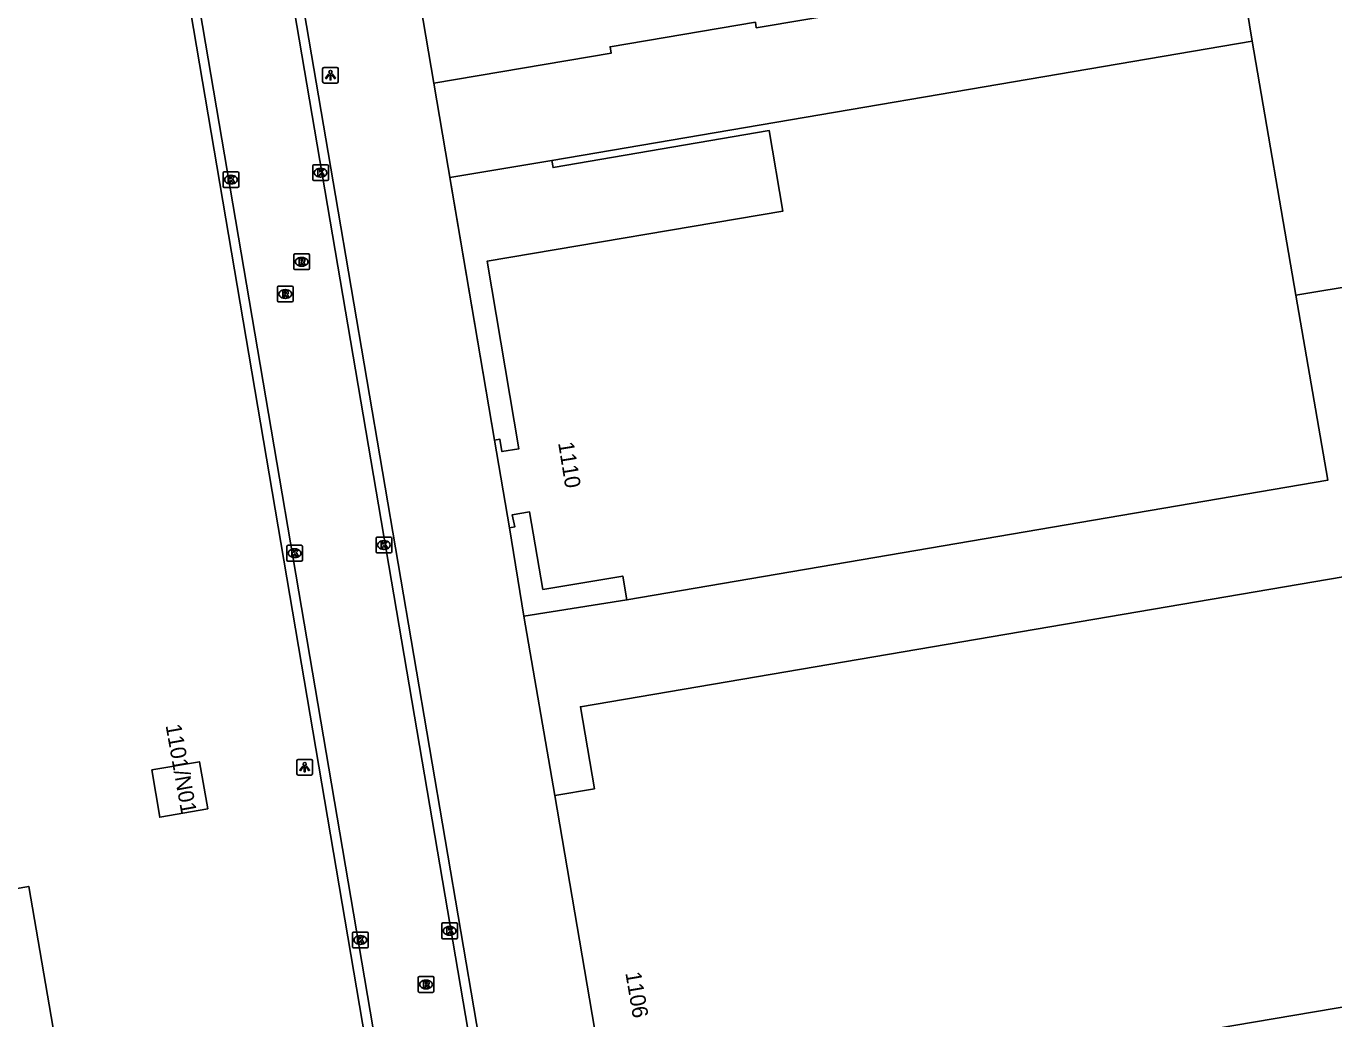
# Model space of a CAD drawing. Extents: x 154324 to 155743, y 382939 to 384183.
# Drawn here: x 154922.8 to 155006.1, y 383284.2 to 383347.4 of the extents above; entities that cross this region are included whole.
import ezdxf

# ---------------------------------------------------------------- set-up
doc = ezdxf.new("R2010")
doc.units = 0
for name, color, linetype in [('IMGEO_Grasland_agrarisch', 7, 'Continuous'), ('IMGEO_Kolk', 7, 'Continuous'), ('IMGEO_Lichtpunt', 7, 'Continuous'), ('IMGEO_Pand', 7, 'Continuous'), ('IMGEO_Pand_nummerreeks', 7, 'Continuous'), ('IMGEO_Pand_overbouw', 7, 'Continuous'), ('IMGEO_Parkeervlak_open', 7, 'Continuous'), ('IMGEO_Rijbaan_lokaal_gesloten', 7, 'Continuous'), ('IMGEO_Rijbaan_lokaal_open', 7, 'Continuous'), ('IMGEO_Rioolput', 7, 'Continuous')]:
    doc.layers.add(name, color=color, linetype=linetype)

msp = doc.modelspace()

# ---------------------------------------------------------------- linework, layer by layer
at = {"layer": 'IMGEO_Grasland_agrarisch'}
for points in [[(155000.868, 383346.436), (154999.878, 383352.447)], [(155062.526, 383340.029), (155003.646, 383330.283)]]:
    msp.add_lwpolyline(points, dxfattribs=at)
at = {"layer": 'IMGEO_Kolk'}
for p, q in [((154941.026, 383337.649), (154941.026, 383338.501)), ((154941.101, 383338.575), (154941.953, 383338.575)), ((154941.514, 383338.355), (154941.539, 383338.355)), ((154942.027, 383338.501), (154942.027, 383337.649)), ((154935.32, 383337.207), (154935.32, 383338.059)), ((154935.395, 383338.133), (154936.247, 383338.133)), ((154935.808, 383337.913), (154935.833, 383337.913)), ((154936.321, 383338.059), (154936.321, 383337.207)), ((154941.953, 383337.575), (154941.101, 383337.575)), ((154941.537, 383337.795), (154941.512, 383337.795)), ((154936.247, 383337.133), (154935.395, 383337.133)), ((154935.831, 383337.353), (154935.806, 383337.353)), ((154939.374, 383313.426), (154939.374, 383314.278)), ((154939.449, 383314.352), (154940.301, 383314.352)), ((154939.862, 383314.132), (154939.887, 383314.132)), ((154940.375, 383314.278), (154940.375, 383313.426)), ((154945.059, 383313.946), (154945.059, 383314.798)), ((154945.134, 383314.872), (154945.986, 383314.872)), ((154945.547, 383314.652), (154945.572, 383314.652)), ((154946.06, 383314.798), (154946.06, 383313.946)), ((154940.301, 383313.352), (154939.449, 383313.352)), ((154939.885, 383313.572), (154939.86, 383313.572)), ((154945.986, 383313.872), (154945.134, 383313.872)), ((154945.57, 383314.092), (154945.545, 383314.092)), ((154949.247, 383289.386), (154949.247, 383290.238)), ((154949.322, 383290.312), (154950.174, 383290.312)), ((154949.735, 383290.092), (154949.76, 383290.092)), ((154950.248, 383290.238), (154950.248, 383289.386)), ((154943.56, 383288.804), (154943.56, 383289.656)), ((154943.635, 383289.73), (154944.487, 383289.73)), ((154944.048, 383289.51), (154944.073, 383289.51)), ((154944.561, 383289.656), (154944.561, 383288.804)), ((154950.174, 383289.312), (154949.322, 383289.312)), ((154949.758, 383289.532), (154949.733, 383289.532)), ((154944.487, 383288.73), (154943.635, 383288.73)), ((154944.071, 383288.95), (154944.046, 383288.95))]:
    msp.add_line(p, q, dxfattribs=at)
for points in [[(154941.026, 383337.649), (154941.026, 383338.501)], [(154941.101, 383338.575), (154941.953, 383338.575)], [(154941.347, 383338.275), (154941.47, 383338.275), (154941.47, 383338.124), (154941.6, 383338.275), (154941.764, 383338.275), (154941.618, 383338.124), (154941.771, 383337.875), (154941.619, 383337.875), (154941.534, 383338.039), (154941.47, 383337.972), (154941.47, 383337.875), (154941.347, 383337.875), (154941.347, 383338.275)], [(154942.027, 383338.501), (154942.027, 383337.649)], [(154935.32, 383337.207), (154935.32, 383338.059)], [(154935.395, 383338.133), (154936.247, 383338.133)], [(154935.641, 383337.833), (154935.764, 383337.833), (154935.764, 383337.682), (154935.894, 383337.833), (154936.058, 383337.833), (154935.912, 383337.682), (154936.065, 383337.433), (154935.913, 383337.433), (154935.828, 383337.597), (154935.764, 383337.53), (154935.764, 383337.433), (154935.641, 383337.433), (154935.641, 383337.833)], [(154936.321, 383338.059), (154936.321, 383337.207)], [(154941.953, 383337.575), (154941.101, 383337.575)], [(154936.247, 383337.133), (154935.395, 383337.133)], [(154939.374, 383313.426), (154939.374, 383314.278)], [(154939.449, 383314.352), (154940.301, 383314.352)], [(154940.375, 383314.278), (154940.375, 383313.426)], [(154945.059, 383313.946), (154945.059, 383314.798)], [(154945.134, 383314.872), (154945.986, 383314.872)], [(154945.38, 383314.572), (154945.503, 383314.572), (154945.503, 383314.421), (154945.633, 383314.572), (154945.797, 383314.572), (154945.651, 383314.421), (154945.804, 383314.172), (154945.652, 383314.172), (154945.567, 383314.336), (154945.503, 383314.269), (154945.503, 383314.172), (154945.38, 383314.172), (154945.38, 383314.572)], [(154946.06, 383314.798), (154946.06, 383313.946)], [(154940.301, 383313.352), (154939.449, 383313.352)], [(154939.695, 383314.052), (154939.818, 383314.052), (154939.818, 383313.901), (154939.948, 383314.052), (154940.112, 383314.052), (154939.966, 383313.901), (154940.119, 383313.652), (154939.967, 383313.652), (154939.882, 383313.816), (154939.818, 383313.749), (154939.818, 383313.652), (154939.695, 383313.652), (154939.695, 383314.052)], [(154945.986, 383313.872), (154945.134, 383313.872)], [(154949.247, 383289.386), (154949.247, 383290.238)], [(154949.322, 383290.312), (154950.174, 383290.312)], [(154949.568, 383290.012), (154949.691, 383290.012), (154949.691, 383289.861), (154949.821, 383290.012), (154949.985, 383290.012), (154949.839, 383289.861), (154949.992, 383289.612), (154949.84, 383289.612), (154949.755, 383289.776), (154949.691, 383289.709), (154949.691, 383289.612), (154949.568, 383289.612), (154949.568, 383290.012)], [(154950.248, 383290.238), (154950.248, 383289.386)], [(154943.56, 383288.804), (154943.56, 383289.656)], [(154943.635, 383289.73), (154944.487, 383289.73)], [(154943.881, 383289.43), (154944.004, 383289.43), (154944.004, 383289.279), (154944.134, 383289.43), (154944.298, 383289.43), (154944.152, 383289.279), (154944.305, 383289.03), (154944.153, 383289.03), (154944.068, 383289.194), (154944.004, 383289.127), (154944.004, 383289.03), (154943.881, 383289.03), (154943.881, 383289.43)], [(154944.561, 383289.656), (154944.561, 383288.804)], [(154950.174, 383289.312), (154949.322, 383289.312)], [(154944.487, 383288.73), (154943.635, 383288.73)]]:
    msp.add_lwpolyline(points, dxfattribs=at)
for centre, start, end in [((154941.103, 383338.499), 91.55205, 178.44795), ((154941.103, 383338.499), 91.55205, 178.44795), ((154941.951, 383338.499), 1.55205, 88.44795), ((154941.951, 383338.499), 1.55205, 88.44795), ((154935.397, 383338.057), 91.55205, 178.44795), ((154935.397, 383338.057), 91.55205, 178.44795), ((154936.245, 383338.057), 1.55205, 88.44795), ((154936.245, 383338.057), 1.55205, 88.44795), ((154941.103, 383337.651), 181.55205, 268.44795), ((154941.103, 383337.651), 181.55205, 268.44795), ((154941.951, 383337.651), 271.55205, 358.44795), ((154941.951, 383337.651), 271.55205, 358.44795), ((154935.397, 383337.209), 181.55205, 268.44795), ((154935.397, 383337.209), 181.55205, 268.44795), ((154936.245, 383337.209), 271.55205, 358.44795), ((154936.245, 383337.209), 271.55205, 358.44795), ((154939.451, 383314.276), 91.55205, 178.44795), ((154939.451, 383314.276), 91.55205, 178.44795), ((154940.299, 383314.276), 1.55205, 88.44795), ((154940.299, 383314.276), 1.55205, 88.44795), ((154945.136, 383314.796), 91.55205, 178.44795), ((154945.136, 383314.796), 91.55205, 178.44795), ((154945.984, 383314.796), 1.55205, 88.44795), ((154945.984, 383314.796), 1.55205, 88.44795), ((154939.451, 383313.428), 181.55205, 268.44795), ((154939.451, 383313.428), 181.55205, 268.44795), ((154940.299, 383313.428), 271.55205, 358.44795), ((154940.299, 383313.428), 271.55205, 358.44795), ((154945.136, 383313.948), 181.55205, 268.44795), ((154945.136, 383313.948), 181.55205, 268.44795), ((154945.984, 383313.948), 271.55205, 358.44795), ((154945.984, 383313.948), 271.55205, 358.44795), ((154949.324, 383290.236), 91.55205, 178.44795), ((154949.324, 383290.236), 91.55205, 178.44795), ((154950.172, 383290.236), 1.55205, 88.44795), ((154950.172, 383290.236), 1.55205, 88.44795), ((154943.637, 383289.654), 91.55205, 178.44795), ((154943.637, 383289.654), 91.55205, 178.44795), ((154944.485, 383289.654), 1.55205, 88.44795), ((154944.485, 383289.654), 1.55205, 88.44795), ((154949.324, 383289.388), 181.55205, 268.44795), ((154949.324, 383289.388), 181.55205, 268.44795), ((154950.172, 383289.388), 271.55205, 358.44795), ((154950.172, 383289.388), 271.55205, 358.44795), ((154943.637, 383288.806), 181.55205, 268.44795), ((154943.637, 383288.806), 181.55205, 268.44795), ((154944.485, 383288.806), 271.55205, 358.44795), ((154944.485, 383288.806), 271.55205, 358.44795)]:
    msp.add_arc(centre, 0.0765, start, end, dxfattribs=at)
for centre, major_axis, ratio, start_param, end_param in [((154941.513, 383338.075), (-0.387, 0.002), 0.722429, 4.712389, 7.853982), ((154941.538, 383338.075), (-0.39, 0.002), 0.717154, 1.570796, 4.712389), ((154935.807, 383337.633), (-0.387, 0.002), 0.722429, 4.712389, 7.853982), ((154935.832, 383337.633), (-0.39, 0.002), 0.717154, 1.570796, 4.712389), ((154939.861, 383313.852), (-0.387, 0.002), 0.722429, 4.712389, 7.853982), ((154939.886, 383313.852), (-0.39, 0.002), 0.717154, 1.570796, 4.712389), ((154945.546, 383314.372), (-0.387, 0.002), 0.722429, 4.712389, 7.853982), ((154945.571, 383314.372), (-0.39, 0.002), 0.717154, 1.570796, 4.712389), ((154949.734, 383289.812), (-0.387, 0.002), 0.722429, 4.712389, 7.853982), ((154949.759, 383289.812), (-0.39, 0.002), 0.717154, 1.570796, 4.712389), ((154944.047, 383289.23), (-0.387, 0.002), 0.722429, 4.712389, 7.853982), ((154944.072, 383289.23), (-0.39, 0.002), 0.717154, 1.570796, 4.712389)]:
    msp.add_ellipse(centre, major_axis=major_axis, ratio=ratio, start_param=start_param, end_param=end_param, dxfattribs=at)
at = {"layer": 'IMGEO_Lichtpunt'}
for p, q in [((154941.66, 383344.683), (154941.66, 383343.876)), ((154941.66, 383344.683), (154941.66, 383343.876)), ((154942.562, 383344.778), (154941.754, 383344.778)), ((154942.562, 383344.778), (154941.754, 383344.778)), ((154942.656, 383343.876), (154942.656, 383344.683)), ((154942.656, 383343.876), (154942.656, 383344.683)), ((154941.754, 383343.782), (154942.562, 383343.782)), ((154941.754, 383343.782), (154942.562, 383343.782)), ((154940.016, 383300.629), (154940.016, 383299.822)), ((154940.016, 383300.629), (154940.016, 383299.822)), ((154940.918, 383300.724), (154940.11, 383300.724)), ((154940.918, 383300.724), (154940.11, 383300.724)), ((154941.012, 383299.822), (154941.012, 383300.629)), ((154941.012, 383299.822), (154941.012, 383300.629)), ((154940.11, 383299.728), (154940.918, 383299.728)), ((154940.11, 383299.728), (154940.918, 383299.728))]:
    msp.add_line(p, q, dxfattribs=at)
for points in [[(154942.034, 383344.347), (154942.073, 383344.319), (154941.885, 383344.057), (154941.847, 383344.084), (154942.034, 383344.347)], [(154942.136, 383344.299), (154942.183, 383344.299), (154942.183, 383343.977), (154942.136, 383343.977), (154942.136, 383344.299)], [(154942.246, 383344.319), (154942.284, 383344.346), (154942.471, 383344.084), (154942.432, 383344.056), (154942.246, 383344.319)], [(154940.39, 383300.293), (154940.429, 383300.265), (154940.241, 383300.003), (154940.203, 383300.03), (154940.39, 383300.293)], [(154940.492, 383300.245), (154940.539, 383300.245), (154940.539, 383299.923), (154940.492, 383299.923), (154940.492, 383300.245)], [(154940.602, 383300.265), (154940.64, 383300.292), (154940.827, 383300.03), (154940.788, 383300.002), (154940.602, 383300.265)]]:
    msp.add_lwpolyline(points, dxfattribs=at)
for centre in [(154942.159, 383344.481), (154940.515, 383300.427)]:
    msp.add_circle(centre, 0.0994, dxfattribs=at)
for centre, start, end in [((154941.754, 383344.683), 90, 180), ((154941.754, 383344.683), 90, 180), ((154942.562, 383344.683), 0, 90), ((154942.562, 383344.683), 0, 90), ((154941.754, 383343.876), 180, 270), ((154941.754, 383343.876), 180, 270), ((154942.562, 383343.876), 270, 0), ((154942.562, 383343.876), 270, 360), ((154940.11, 383300.629), 90, 180), ((154940.11, 383300.629), 90, 180), ((154940.918, 383300.629), 0, 90), ((154940.918, 383300.629), 0, 90), ((154940.11, 383299.822), 180, 270), ((154940.11, 383299.822), 180, 270), ((154940.918, 383299.822), 270, 0), ((154940.918, 383299.822), 270, 360)]:
    msp.add_arc(centre, 0.0946, start, end, dxfattribs=at)
at = {"layer": 'IMGEO_Pand'}
for points in [[(154948.75, 383343.779), (154944.993, 383365.869), (154944.925, 383366.268), (154965.468, 383369.782), (154964.539, 383375.316)], [(154999.878, 383352.447), (154969.278, 383347.303), (154969.219, 383347.653), (154959.969, 383346.088), (154960.036, 383345.69), (154948.75, 383343.779)], [(154952.604, 383321.047), (154952.949, 383321.105), (154953.081, 383320.316), (154954.156, 383320.496), (154952.132, 383332.433), (154970.973, 383335.629), (154970.103, 383340.756), (154956.338, 383338.399), (154956.261, 383338.852), (155000.868, 383346.436)], [(155003.646, 383330.283), (155000.868, 383346.436)], [(154841.851, 383345.321), (154852.853, 383280.684), (154854.938, 383281.039), (154922.938, 383292.639), (154927.907, 383263.724), (154927.942, 383263.507), (154923.572, 383260.288), (154926.413, 383256.439), (154924.778, 383255.22), (154927.17, 383252.008), (154925.538, 383250.794), (154927.916, 383247.585), (154926.283, 383246.367), (154929.131, 383242.58), (154931.183, 383244.108), (154931.296, 383243.969), (154938.169, 383203.279), (154923.048, 383200.725), (154925.906, 383183.809)], [(155003.646, 383330.283), (155005.673, 383318.494), (154961.037, 383310.872), (154960.776, 383312.399), (154955.689, 383311.55), (154954.834, 383316.483), (154953.74, 383316.294), (154953.892, 383315.524), (154953.555, 383315.462)], [(154953.555, 383315.462), (154952.604, 383321.047)], [(154956.449, 383298.428), (154958.963, 383298.857), (154958.072, 383304.074), (155006.663, 383312.344), (155011.213, 383285.747), (154970.24, 383278.793), (154971.18, 383273.272), (154961.04, 383271.548)], [(154930.785, 383300.07), (154933.808, 383300.574), (154934.341, 383297.582), (154931.29, 383297.039), (154930.785, 383300.07)], [(154961.04, 383271.548), (154956.449, 383298.428)]]:
    msp.add_lwpolyline(points, dxfattribs=at)
at = {"layer": 'IMGEO_Pand_overbouw'}
for points in [[(154956.261, 383338.852), (154949.764, 383337.775), (154952.604, 383321.047), (154952.949, 383321.105), (154953.081, 383320.316), (154954.156, 383320.496), (154952.132, 383332.433), (154970.973, 383335.629), (154970.103, 383340.756), (154956.338, 383338.399)], [(154961.037, 383310.872), (154960.776, 383312.399), (154955.689, 383311.55), (154954.834, 383316.483), (154953.74, 383316.294), (154953.892, 383315.524), (154953.555, 383315.462), (154954.479, 383309.839)]]:
    msp.add_lwpolyline(points, close=True, dxfattribs=at)
at = {"layer": 'IMGEO_Parkeervlak_open'}
for points in [[(154948.75, 383343.779), (154952.604, 383321.047)], [(154956.449, 383298.428), (154954.479, 383309.839), (154953.555, 383315.462)]]:
    msp.add_lwpolyline(points, dxfattribs=at)
at = {"layer": 'IMGEO_Rijbaan_lokaal_gesloten'}
for points in [[(154937.891, 383359.922), (154961.836, 383219.4)], [(154958.22, 383204.737), (154957.681, 383208.024), (154956.051, 383217.962), (154933.662, 383349.45), (154932.04, 383358.964)]]:
    msp.add_lwpolyline(points, dxfattribs=at)
at = {"layer": 'IMGEO_Rijbaan_lokaal_open'}
for points in [[(154962.428, 383219.494), (154942.478, 383336.616), (154938.491, 383360.02)], [(154957.636, 383205.007), (154955.126, 383219.621), (154933.063, 383349.385), (154931.446, 383358.867)]]:
    msp.add_lwpolyline(points, dxfattribs=at)
at = {"layer": 'IMGEO_Rioolput'}
for p, q in [((154939.823, 383331.974), (154939.823, 383332.826)), ((154939.898, 383332.9), (154940.75, 383332.9)), ((154940.311, 383332.68), (154940.336, 383332.68)), ((154940.824, 383332.826), (154940.824, 383331.974)), ((154940.75, 383331.9), (154939.898, 383331.9)), ((154940.334, 383332.12), (154940.309, 383332.12)), ((154938.778, 383329.924), (154938.778, 383330.776)), ((154938.853, 383330.85), (154939.705, 383330.85)), ((154939.779, 383330.776), (154939.779, 383329.924)), ((154939.289, 383330.07), (154939.264, 383330.07)), ((154939.266, 383330.63), (154939.291, 383330.63)), ((154939.705, 383329.85), (154938.853, 383329.85)), ((154947.746, 383285.971), (154947.746, 383286.823)), ((154947.821, 383286.897), (154948.673, 383286.897)), ((154948.234, 383286.677), (154948.259, 383286.677)), ((154948.747, 383286.823), (154948.747, 383285.971)), ((154948.673, 383285.897), (154947.821, 383285.897)), ((154948.257, 383286.117), (154948.232, 383286.117))]:
    msp.add_line(p, q, dxfattribs=at)
for points in [[(154939.823, 383331.974), (154939.823, 383332.826)], [(154939.898, 383332.9), (154940.75, 383332.9)], [(154940.412, 383332.598), (154940.16, 383332.6), (154940.16, 383332.2)], [(154940.338, 383332.519), (154940.284, 383332.519), (154940.284, 383332.438)], [(154940.284, 383332.438), (154940.336, 383332.438)], [(154940.824, 383332.826), (154940.824, 383331.974)], [(154940.75, 383331.9), (154939.898, 383331.9)], [(154940.16, 383332.2), (154940.284, 383332.2), (154940.284, 383332.362), (154940.295, 383332.362)], [(154940.342, 383332.333), (154940.413, 383332.2), (154940.553, 383332.2), (154940.488, 383332.326)], [(154938.778, 383329.924), (154938.778, 383330.776)], [(154938.853, 383330.85), (154939.705, 383330.85)], [(154939.779, 383330.776), (154939.779, 383329.924)], [(154939.367, 383330.548), (154939.115, 383330.55), (154939.115, 383330.15)], [(154939.115, 383330.15), (154939.239, 383330.15), (154939.239, 383330.312), (154939.25, 383330.312)], [(154939.293, 383330.469), (154939.239, 383330.469), (154939.239, 383330.388)], [(154939.239, 383330.388), (154939.291, 383330.388)], [(154939.297, 383330.283), (154939.368, 383330.15), (154939.508, 383330.15), (154939.443, 383330.276)], [(154939.705, 383329.85), (154938.853, 383329.85)], [(154947.746, 383285.971), (154947.746, 383286.823)], [(154947.821, 383286.897), (154948.673, 383286.897)], [(154948.747, 383286.823), (154948.747, 383285.971)], [(154948.673, 383285.897), (154947.821, 383285.897)], [(154948.335, 383286.595), (154948.083, 383286.597), (154948.083, 383286.197)], [(154948.083, 383286.197), (154948.207, 383286.197), (154948.207, 383286.359), (154948.218, 383286.359)], [(154948.261, 383286.516), (154948.207, 383286.516), (154948.207, 383286.435)], [(154948.207, 383286.435), (154948.259, 383286.435)], [(154948.265, 383286.33), (154948.336, 383286.197), (154948.476, 383286.197), (154948.411, 383286.323)]]:
    msp.add_lwpolyline(points, dxfattribs=at)
for centre, radius, start, end in [((154939.9, 383332.824), 0.0765, 91.55205, 178.44795), ((154939.9, 383332.824), 0.0765, 91.55205, 178.44795), ((154940.32, 383332.627), 0.19, 274.7715, 282.96867), ((154940.344, 383332.423), 0.0964, 77.00612, 93.18647), ((154940.358, 383332.48), 0.0378, 276.66336, 79.67722), ((154940.411, 383332.488), 0.109, 350.36119, 89.41601), ((154940.409, 383332.488), 0.112, 277.58423, 350.98172), ((154940.748, 383332.824), 0.0765, 1.55205, 88.44795), ((154940.748, 383332.824), 0.0765, 1.55205, 88.44795), ((154939.9, 383331.976), 0.0765, 181.55205, 268.44795), ((154939.9, 383331.976), 0.0765, 181.55205, 268.44795), ((154940.294, 383332.309), 0.0533, 26.02933, 88.69889), ((154940.393, 383332.273), 0.108, 29.51342, 73.79051), ((154940.748, 383331.976), 0.0765, 271.55205, 358.44795), ((154940.748, 383331.976), 0.0765, 271.55205, 358.44795), ((154938.855, 383330.774), 0.0765, 91.55205, 178.44795), ((154938.855, 383330.774), 0.0765, 91.55205, 178.44795), ((154939.703, 383330.774), 0.0765, 1.55205, 88.44795), ((154939.703, 383330.774), 0.0765, 1.55205, 88.44795), ((154939.249, 383330.259), 0.0533, 26.02933, 88.69889), ((154939.275, 383330.577), 0.19, 274.7715, 282.96867), ((154939.299, 383330.373), 0.0964, 77.00612, 93.18647), ((154939.313, 383330.43), 0.0378, 276.66336, 79.67722), ((154939.366, 383330.438), 0.109, 350.36119, 89.41601), ((154939.364, 383330.438), 0.112, 277.58423, 350.98172), ((154939.348, 383330.223), 0.108, 29.51342, 73.79051), ((154938.855, 383329.926), 0.0765, 181.55205, 268.44795), ((154938.855, 383329.926), 0.0765, 181.55205, 268.44795), ((154939.703, 383329.926), 0.0765, 271.55205, 358.44795), ((154939.703, 383329.926), 0.0765, 271.55205, 358.44795), ((154947.823, 383286.821), 0.0765, 91.55205, 178.44795), ((154947.823, 383286.821), 0.0765, 91.55205, 178.44795), ((154948.671, 383286.821), 0.0765, 1.55205, 88.44795), ((154948.671, 383286.821), 0.0765, 1.55205, 88.44795), ((154947.823, 383285.973), 0.0765, 181.55205, 268.44795), ((154947.823, 383285.973), 0.0765, 181.55205, 268.44795), ((154948.217, 383286.306), 0.0533, 26.02933, 88.69889), ((154948.243, 383286.624), 0.19, 274.7715, 282.96867), ((154948.267, 383286.42), 0.0964, 77.00612, 93.18647), ((154948.281, 383286.477), 0.0378, 276.66336, 79.67722), ((154948.334, 383286.485), 0.109, 350.36119, 89.41601), ((154948.332, 383286.485), 0.112, 277.58423, 350.98172), ((154948.316, 383286.27), 0.108, 29.51342, 73.79051), ((154948.671, 383285.973), 0.0765, 271.55205, 358.44795), ((154948.671, 383285.973), 0.0765, 271.55205, 358.44795)]:
    msp.add_arc(centre, radius, start, end, dxfattribs=at)
for centre, major_axis, ratio, start_param, end_param in [((154940.31, 383332.4), (-0.387, 0.002), 0.722429, 4.712389, 7.853982), ((154940.335, 383332.4), (-0.39, 0.002), 0.717154, 1.570796, 4.712389), ((154939.265, 383330.35), (-0.387, 0.002), 0.722429, 4.712389, 7.853982), ((154939.29, 383330.35), (-0.39, 0.002), 0.717154, 1.570796, 4.712389), ((154948.233, 383286.397), (-0.387, 0.002), 0.722429, 4.712389, 7.853982), ((154948.258, 383286.397), (-0.39, 0.002), 0.717154, 1.570796, 4.712389)]:
    msp.add_ellipse(centre, major_axis=major_axis, ratio=ratio, start_param=start_param, end_param=end_param, dxfattribs=at)

# ---------------------------------------------------------------- texts
at = {"layer": 'IMGEO_Pand_nummerreeks'}
for s, rotation, p in [('1110', 279.28457, (154956.652, 383320.871)), ('1101/N01', 280.10844, (154931.653, 383302.889)), ('1106', 279.69162, (154960.935, 383287.131))]:
    msp.add_text(s, height=1, rotation=rotation, dxfattribs=at).set_placement(p)

doc.saveas('drawing.dxf')
